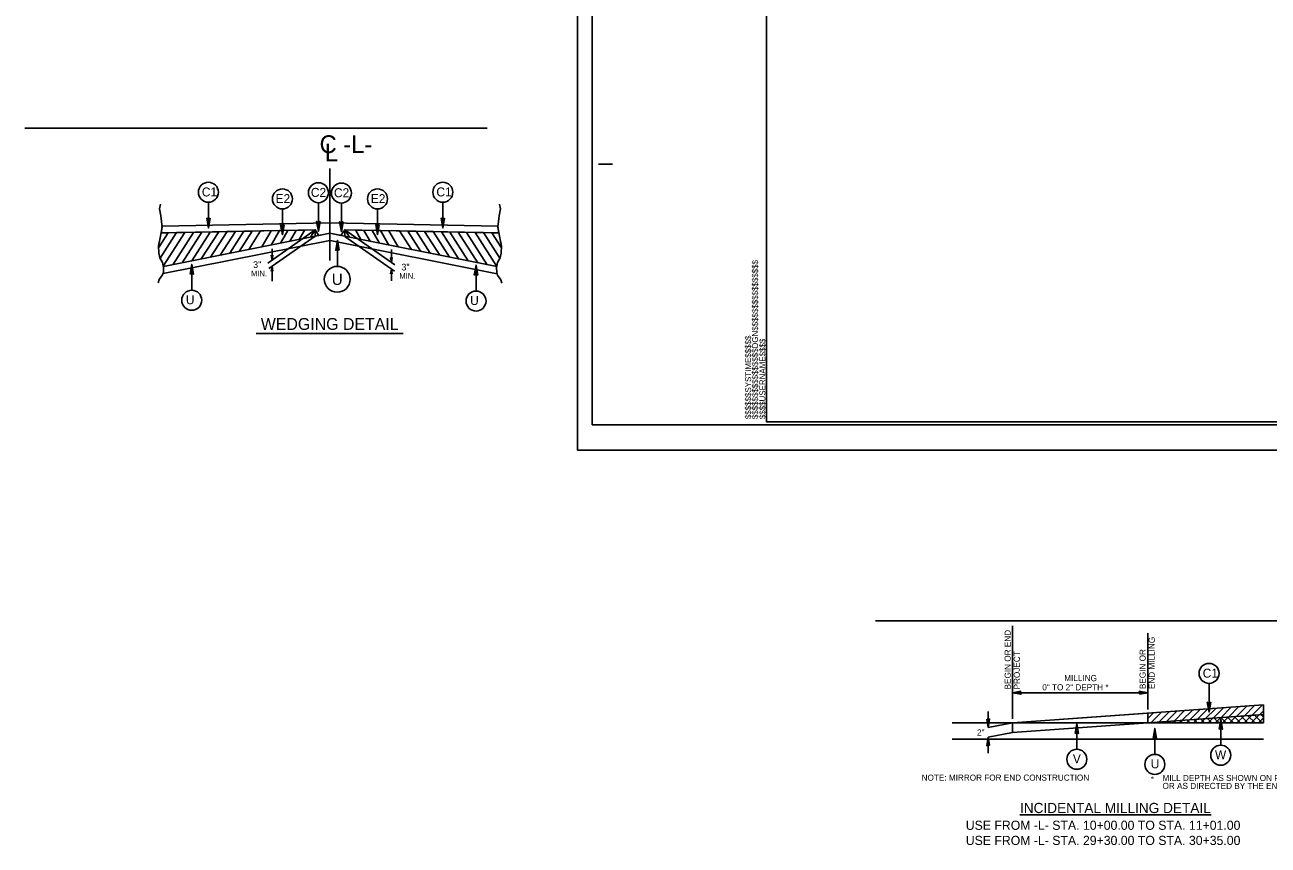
# Model space of a CAD drawing. Extents: x 2111095 to 2115970, y 670428 to 672393.
# Drawn here: x 2111095 to 2112193, y 670767 to 671492 of the extents above; entities that cross this region are included whole.
import ezdxf

# ---------------------------------------------------------------- set-up
doc = ezdxf.new("R2010")
doc.units = 0
for name, color, linetype in [('Old_Level_1', 7, 'Continuous'), ('Old_Level_11', 7, 'Continuous'), ('Old_Level_19', 7, 'Continuous'), ('Old_Level_20', 7, 'Continuous'), ('Old_Level_21', 7, 'Continuous'), ('Old_Level_3', 7, 'Continuous'), ('Prop Dimension', 7, 'Continuous'), ('Prop DSN Text', 7, 'Continuous'), ('Prop Shade Medium', 7, 'Continuous'), ('Sheet Cutting Line CELL', 7, 'Continuous'), ('Sheet Plot Border Inside CELL', 7, 'Continuous'), ('Sheet Plot Border Outside CELL', 7, 'Continuous'), ('Sheet Typical CELL', 7, 'Continuous')]:
    doc.layers.add(name, color=color, linetype=linetype)

msp = doc.modelspace()

# ---------------------------------------------------------------- linework, layer by layer
at = {"layer": 'Old_Level_1'}
for p, q in [((2111364.8, 671283.4), (2111364.8, 671364.8)), ((2111312.9, 671309.8), (2111304.6, 671295.6)), ((2111320.3, 671310), (2111312.9, 671297.2)), ((2111327.6, 671310.1), (2111321.1, 671298.9)), ((2111335, 671310.1), (2111329.4, 671300.5)), ((2111342.5, 671310.5), (2111337.6, 671302.2)), ((2111378, 671310.5), (2111422.1, 671279.6)), ((2111387.2, 671310.5), (2111392, 671302.2)), ((2111394.6, 671310.1), (2111400.2, 671300.5)), ((2111402, 671310.1), (2111408.6, 671298.9)), ((2111409.3, 671309.9), (2111416.8, 671297.2)), ((2111416.8, 671309.8), (2111425.1, 671295.6)), ((2111364.8, 671301.3), (2111217.5, 671271.9)), ((2111351.6, 671305), (2111310.7, 671276.3)), ((2111364.9, 671301.3), (2111512.5, 671271.8)), ((2111378, 671304.6), (2111421.7, 671274.1)), ((2111313.6, 671283.9), (2111312.9, 671288.2)), ((2111313.6, 671287.7), (2111312.9, 671288.2)), ((2111313.6, 671283.9), (2111313, 671288.1)), ((2111313.1, 671288.1), (2111313.6, 671283.9)), ((2111313.6, 671283.9), (2111313.2, 671288)), ((2111313.3, 671287.9), (2111313.6, 671283.9)), ((2111313.6, 671283.9), (2111313.4, 671287.8)), ((2111313.5, 671287.7), (2111313.6, 671283.9)), ((2111313.6, 671293.8), (2111313.6, 671283.9)), ((2111313.6, 671283.9), (2111314.4, 671288.2)), ((2111314.4, 671288.2), (2111313.6, 671287.7)), ((2111314.3, 671288.1), (2111313.6, 671283.9)), ((2111313.6, 671283.9), (2111314.2, 671288.1)), ((2111314.1, 671288), (2111313.6, 671283.9)), ((2111313.6, 671283.9), (2111314, 671287.9)), ((2111313.9, 671287.8), (2111313.6, 671283.9)), ((2111313.6, 671283.9), (2111313.8, 671287.7)), ((2111313.6, 671287.7), (2111313.6, 671283.9)), ((2111419, 671293.2), (2111419, 671281.8)), ((2111313.6, 671278.4), (2111312.9, 671274)), ((2111313, 671274.1), (2111313.6, 671278.4)), ((2111313.6, 671278.4), (2111313.1, 671274.2)), ((2111313.2, 671274.3), (2111313.6, 671278.4)), ((2111313.6, 671278.4), (2111313.3, 671274.4)), ((2111313.4, 671274.4), (2111313.6, 671278.4)), ((2111313.6, 671278.4), (2111313.5, 671274.5)), ((2111313.6, 671278.4), (2111313.6, 671265.4)), ((2111313.6, 671278.4), (2111314.4, 671274)), ((2111313.6, 671274.6), (2111313.6, 671278.4)), ((2111313.8, 671274.5), (2111313.6, 671278.4)), ((2111313.6, 671278.4), (2111313.9, 671274.4)), ((2111314, 671274.4), (2111313.6, 671278.4)), ((2111313.6, 671278.4), (2111314.1, 671274.3)), ((2111314.2, 671274.2), (2111313.6, 671278.4)), ((2111313.6, 671278.4), (2111314.3, 671274.1)), ((2111419, 671281.8), (2111418.2, 671286.2)), ((2111419, 671285.6), (2111418.2, 671286.2)), ((2111419, 671281.8), (2111418.3, 671286.1)), ((2111418.4, 671286), (2111419, 671281.8)), ((2111419, 671281.8), (2111418.6, 671285.9)), ((2111418.7, 671285.9), (2111419, 671281.8)), ((2111419, 671281.8), (2111418.8, 671285.8)), ((2111418.9, 671285.7), (2111419, 671281.8)), ((2111419, 671281.8), (2111419.8, 671286.2)), ((2111419.8, 671286.2), (2111419, 671285.6)), ((2111419.7, 671286.1), (2111419, 671281.8)), ((2111419, 671281.8), (2111419.5, 671286)), ((2111419.4, 671285.9), (2111419, 671281.8)), ((2111419, 671281.8), (2111419.3, 671285.9)), ((2111419.2, 671285.8), (2111419, 671281.8)), ((2111419, 671281.8), (2111419.1, 671285.7)), ((2111419, 671285.6), (2111419, 671281.8)), ((2111312.9, 671274), (2111313.6, 671274.6)), ((2111313.6, 671274.6), (2111314.4, 671274)), ((2111419, 671275.9), (2111418.2, 671271.6)), ((2111418.2, 671271.6), (2111419, 671272.1)), ((2111418.3, 671271.7), (2111419, 671275.9)), ((2111419, 671275.9), (2111418.4, 671271.7)), ((2111418.6, 671271.8), (2111419, 671275.9)), ((2111419, 671275.9), (2111418.7, 671271.9)), ((2111418.8, 671272), (2111419, 671275.9)), ((2111419, 671275.9), (2111418.9, 671272)), ((2111419, 671275.9), (2111419, 671265.7)), ((2111419, 671275.9), (2111419.8, 671271.6)), ((2111419, 671272.1), (2111419, 671275.9)), ((2111419.1, 671272), (2111419, 671275.9)), ((2111419, 671275.9), (2111419.2, 671272)), ((2111419.3, 671271.9), (2111419, 671275.9)), ((2111419, 671275.9), (2111419.4, 671271.8)), ((2111419.5, 671271.7), (2111419, 671275.9)), ((2111419, 671275.9), (2111419.7, 671271.7)), ((2111419, 671272.1), (2111419.8, 671271.6)), ((2112189.5, 670891), (2111967.7, 670875.1)), ((2112087.2, 670875.1), (2112087.2, 670883.7)), ((2112189.5, 670882.5), (2112087.2, 670875.1)), ((2112189.5, 670875.1), (2112189.5, 670891)), ((2112189.5, 670875.1), (2111914.5, 670875.1)), ((2112087.2, 670875.1), (2111967.7, 670866.6)), ((2111967.7, 670866.6), (2111967.7, 670875.1)), ((2112189.5, 670860.7), (2111914.5, 670860.7))]:
    msp.add_line(p, q, dxfattribs=at)
for points in [[(2111215.1, 671333.4), (2111214.3, 671329.1), (2111215.5, 671322.9), (2111216.5, 671312.9), (2111215.1, 671305), (2111213.4, 671296.4), (2111213.5, 671290), (2111214.6, 671285.9), (2111216.9, 671281.8), (2111217.7, 671277.3), (2111217.6, 671272.9), (2111216.8, 671270.8), (2111214, 671266.6), (2111213.1, 671263.7)], [(2111514.6, 671333.4), (2111515.4, 671329), (2111514.2, 671322.9), (2111513.1, 671312.9), (2111514.6, 671305), (2111516.3, 671296.4), (2111516.1, 671290), (2111515.1, 671285.9), (2111512.7, 671281.8), (2111511.9, 671277.3), (2111512.1, 671272.8), (2111512.8, 671270.7), (2111515.6, 671266.5), (2111516.5, 671263.6)], [(2111267.7, 671288.2), (2111281.2, 671309.2)], [(2111276.3, 671289.9), (2111288.8, 671309.4)], [(2111284.6, 671291.6), (2111296.2, 671309.5)], [(2111293, 671293.3), (2111303.5, 671309.7)], [(2111436.7, 671293.2), (2111426.1, 671309.7)], [(2111445, 671291.6), (2111433.5, 671309.5)], [(2111453.4, 671289.9), (2111440.9, 671309.4)], [(2111461.9, 671288.2), (2111448.4, 671309.2)], [(2111213.4, 671294.7), (2111222, 671308)], [(2111217.6, 671278.2), (2111216.9, 671281.8), (2111214.6, 671285.9), (2111213.5, 671290), (2111213.4, 671296.4), (2111214.2, 671300.4)], [(2111214.8, 671285.5), (2111229.3, 671308.2)], [(2111217.5, 671278.4), (2111236.7, 671308.3)], [(2111226, 671279.8), (2111244.2, 671308.3)], [(2111234.3, 671281.5), (2111251.6, 671308.4)], [(2111242.7, 671283.2), (2111258.9, 671308.6)], [(2111251, 671284.9), (2111266.5, 671308.9)], [(2111259.4, 671286.5), (2111273.9, 671309.1)], [(2111470.3, 671286.5), (2111455.8, 671309.1)], [(2111478.6, 671284.8), (2111463.2, 671308.9)], [(2111487, 671283.2), (2111470.7, 671308.6)], [(2111495.3, 671281.5), (2111478.1, 671308.4)], [(2111503.7, 671279.8), (2111485.5, 671308.3)], [(2111512.3, 671278.1), (2111492.9, 671308.3)], [(2111514.8, 671285.5), (2111500.3, 671308.2)], [(2111516.2, 671294.7), (2111507.7, 671308)], [(2111512.1, 671278.1), (2111512.7, 671281.8), (2111515.1, 671285.9), (2111516.1, 671290), (2111516.3, 671296.4), (2111515.5, 671300.4)]]:
    msp.add_lwpolyline(points, dxfattribs=at)
at = {"layer": 'Old_Level_11'}
for p, q in [((2111257.4, 671334.9), (2111257.4, 671312.1)), ((2111354.6, 671334.6), (2111354.6, 671309.3)), ((2111374.9, 671334.3), (2111374.9, 671308.9)), ((2111464.5, 671334.9), (2111464.5, 671312.1)), ((2111322.8, 671329.1), (2111322.8, 671306.3)), ((2111406.8, 671329.1), (2111406.8, 671306.3)), ((2111215.6, 671307.9), (2111216.5, 671313.8)), ((2111351.8, 671310.6), (2111215.6, 671307.9)), ((2111351.8, 671310.6), (2111215.6, 671307.9)), ((2111364.8, 671316.8), (2111216.5, 671313.8)), ((2111216.5, 671313.8), (2111364.8, 671316.8)), ((2111351.6, 671310.5), (2111309.8, 671281.2)), ((2111347.6, 671304.2), (2111351.6, 671310.5)), ((2111351.6, 671310.5), (2111351.6, 671305)), ((2111355.1, 671305.7), (2111351.8, 671310.6)), ((2111351.8, 671310.4), (2111355.1, 671305.7)), ((2111364.8, 671316.8), (2111513.2, 671313.8)), ((2111364.8, 671316.8), (2111513.2, 671313.8)), ((2111377.9, 671310.6), (2111374.5, 671305.7)), ((2111377.9, 671310.6), (2111374.5, 671305.7)), ((2111377.7, 671310.5), (2111377.9, 671310.5)), ((2111377.9, 671310.6), (2111514, 671307.8)), ((2111514, 671307.8), (2111377.9, 671310.6)), ((2111382.1, 671304.2), (2111378, 671310.5)), ((2111378, 671310.5), (2111378, 671305)), ((2111513.2, 671313.8), (2111514, 671307.8)), ((2111365, 671307.7), (2111217.6, 671278.2)), ((2111364.6, 671307.7), (2111355.1, 671305.7)), ((2111364.6, 671307.7), (2111512.1, 671278.1)), ((2111374.5, 671305.7), (2111364.6, 671307.7)), ((2111242.7, 671257.2), (2111242.7, 671280)), ((2111493.8, 671256.5), (2111493.8, 671279.4)), ((2111299.6, 671219.1), (2111429.4, 671219.1)), ((2111967.7, 670878.8), (2111967.7, 670961)), ((2112087.2, 670887), (2112087.2, 670954.4)), ((2112141.3, 670910), (2112141.3, 670884.7)), ((2112087.2, 670901.8), (2111967.7, 670901.8)), ((2111946.2, 670871.1), (2111946.2, 670885.1)), ((2111967.7, 670875.1), (2111946.2, 670871.1)), ((2112024.5, 670851.8), (2112024.5, 670874.6)), ((2112093.4, 670847.4), (2112093.4, 670870.2)), ((2112151.6, 670855.5), (2112151.6, 670878.3)), ((2111967.7, 670866.6), (2111946.2, 670862.5)), ((2111946.2, 670848.5), (2111946.2, 670862.5)), ((2111974.3, 670793.8), (2112143.1, 670793.8))]:
    msp.add_line(p, q, dxfattribs=at)
for points in [[(2111258.9, 671320.8), (2111257.4, 671312.1), (2111255.9, 671320.8), (2111257.4, 671319.7)], [(2111466, 671320.8), (2111464.5, 671312.1), (2111463, 671320.8), (2111464.5, 671319.7)], [(2111324.3, 671315), (2111322.8, 671306.3), (2111321.2, 671315), (2111322.8, 671313.9)], [(2111356.1, 671318), (2111354.6, 671309.3), (2111353, 671318), (2111354.6, 671316.9)], [(2111376.4, 671317.6), (2111374.9, 671308.9), (2111373.3, 671317.7), (2111374.9, 671316.6)], [(2111408.3, 671315), (2111406.8, 671306.3), (2111405.2, 671315), (2111406.8, 671313.9)], [(2111241.2, 671271.3), (2111242.7, 671280), (2111244.2, 671271.3), (2111242.7, 671272.4)], [(2111492.3, 671270.7), (2111493.8, 671279.4), (2111495.3, 671270.6), (2111493.8, 671271.8)], [(2111975.1, 670903.1), (2111967.7, 670901.8), (2111975.1, 670900.5), (2111974.2, 670901.8)], [(2112079.8, 670900.5), (2112087.2, 670901.8), (2112079.7, 670903.1), (2112080.7, 670901.8)], [(2112142.8, 670893.4), (2112141.3, 670884.7), (2112139.7, 670893.4), (2112141.3, 670892.3)], [(2111944.9, 670878.5), (2111946.2, 670871.1), (2111947.5, 670878.5), (2111946.2, 670877.6)], [(2112023, 670865.9), (2112024.5, 670874.6), (2112026, 670865.9), (2112024.5, 670867)], [(2112091.9, 670861.5), (2112093.4, 670870.2), (2112095, 670861.5), (2112093.4, 670862.6)], [(2112150.1, 670869.6), (2112151.6, 670878.3), (2112153.1, 670869.6), (2112151.6, 670870.7)], [(2111947.5, 670855.1), (2111946.2, 670862.5), (2111944.9, 670855), (2111946.2, 670856)]]:
    msp.add_lwpolyline(points, close=True, dxfattribs=at)
for centre in [(2111257.4, 671343.8), (2111322.8, 671337.9), (2111354.6, 671343.4), (2111374.9, 671343.1), (2111406.8, 671337.9), (2111464.5, 671343.8), (2111242.7, 671248.4), (2111493.8, 671247.7), (2112141.3, 670918.9), (2112024.5, 670843), (2112151.6, 670846.6), (2112093.4, 670838.5)]:
    msp.add_circle(centre, 8.84, dxfattribs=at)
at = {"layer": 'Old_Level_19'}
for p, q in [((2111750.5, 671446.9), (2111750.5, 671141)), ((2111095.3, 671400.3), (2111503.5, 671400.3)), ((2111750.5, 671141), (2112120.6, 671141)), ((2111846.6, 670965.3), (2112254.8, 670965.3))]:
    msp.add_line(p, q, dxfattribs=at)
at = {"layer": 'Prop DSN Text'}
msp.add_line((2111371.5, 671278.3), (2111371.5, 671301.4), dxfattribs=at)
msp.add_lwpolyline([(2111373, 671292.5), (2111371.5, 671293.6), (2111369.9, 671292.5), (2111371.5, 671301.4)], close=True, dxfattribs=at)
msp.add_circle((2111371.2, 671266.9), 11.4, dxfattribs=at)
at = {"layer": 'Prop Shade Medium'}
for p, q in [((2112092.3, 670884.1), (2112087.2, 670878.9)), ((2112099.2, 670884.5), (2112090, 670875.3)), ((2112106, 670885), (2112096.8, 670875.8)), ((2112112.9, 670885.5), (2112103.7, 670876.3)), ((2112119.7, 670886), (2112110.5, 670876.8)), ((2112126.6, 670886.5), (2112117.4, 670877.3)), ((2112133.4, 670887), (2112124.2, 670877.8)), ((2112140.3, 670887.5), (2112131.1, 670878.3)), ((2112147.2, 670888), (2112137.9, 670878.8)), ((2112154, 670888.5), (2112144.8, 670879.3)), ((2112160.9, 670889), (2112151.6, 670879.7)), ((2112167.7, 670889.5), (2112158.5, 670880.2)), ((2112174.6, 670889.9), (2112165.4, 670880.7)), ((2112171.9, 670881.2), (2112165.8, 670875.1)), ((2112175.5, 670875.1), (2112169.6, 670881)), ((2112181.4, 670890.4), (2112172.2, 670881.2)), ((2112178.7, 670881.7), (2112172.2, 670875.1)), ((2112181.9, 670875.1), (2112175.5, 670881.5)), ((2112185.6, 670882.2), (2112178.6, 670875.1)), ((2112188.3, 670890.9), (2112179.1, 670881.7)), ((2112188.2, 670875.1), (2112181.5, 670881.9)), ((2112189.5, 670885.8), (2112185.9, 670882.2)), ((2112189.5, 670880.2), (2112187.4, 670882.3)), ((2112089.6, 670875.3), (2112089.5, 670875.1)), ((2112092.8, 670875.1), (2112092.4, 670875.5)), ((2112096.5, 670875.8), (2112095.8, 670875.1)), ((2112099.1, 670875.1), (2112098.3, 670875.9)), ((2112103.4, 670876.3), (2112102.2, 670875.1)), ((2112105.5, 670875.1), (2112104.3, 670876.4)), ((2112110.2, 670876.8), (2112108.6, 670875.1)), ((2112111.9, 670875.1), (2112110.2, 670876.8)), ((2112117.1, 670877.3), (2112114.9, 670875.1)), ((2112118.2, 670875.1), (2112116.2, 670877.2)), ((2112123.9, 670877.8), (2112121.3, 670875.1)), ((2112124.6, 670875.1), (2112122.1, 670877.6)), ((2112130.8, 670878.3), (2112127.7, 670875.1)), ((2112131, 670875.1), (2112128, 670878.1)), ((2112137.6, 670878.7), (2112134, 670875.1)), ((2112137.3, 670875.1), (2112134, 670878.5)), ((2112143.7, 670875.1), (2112139.9, 670878.9)), ((2112144.5, 670879.2), (2112140.4, 670875.1)), ((2112150.1, 670875.1), (2112145.9, 670879.3)), ((2112151.3, 670879.7), (2112146.7, 670875.1)), ((2112156.4, 670875.1), (2112151.8, 670879.8)), ((2112158.2, 670880.2), (2112153.1, 670875.1)), ((2112162.8, 670875.1), (2112157.7, 670880.2)), ((2112165, 670880.7), (2112159.5, 670875.1)), ((2112169.1, 670875.1), (2112163.7, 670880.6)), ((2112189.5, 670879.7), (2112184.9, 670875.1))]:
    msp.add_line(p, q, dxfattribs=at)
for points in [[(2111303.5, 671309.6), (2111320.3, 671310), (2111342.4, 671310.4), (2111351.8, 671310.6), (2111355.1, 671305.7), (2111364.6, 671307.7), (2111364.8, 671307.6), (2111364.8, 671307.6), (2111364.8, 671316.8), (2111364.8, 671316.8), (2111216.5, 671313.8), (2111216.4, 671313.7), (2111216.5, 671312.9), (2111215.6, 671308), (2111215.6, 671307.9), (2111221.9, 671308), (2111229.3, 671308.1), (2111236.7, 671308.3), (2111266.4, 671308.9), (2111273.8, 671309), (2111281.2, 671309.2), (2111288.7, 671309.3), (2111296.1, 671309.5), (2111303.5, 671309.6)], [(2111426.2, 671309.6), (2111433.5, 671309.5), (2111440.9, 671309.3), (2111448.5, 671309.2), (2111455.8, 671309), (2111463.2, 671308.9), (2111493, 671308.3), (2111500.3, 671308.1), (2111507.7, 671308), (2111514, 671307.8), (2111513.1, 671312.9), (2111513.2, 671313.7), (2111513.2, 671313.8), (2111364.8, 671316.8), (2111364.8, 671316.8), (2111364.8, 671307.6), (2111364.8, 671307.6), (2111374.5, 671305.7), (2111377.9, 671310.5), (2111377.9, 671310.6), (2111387.2, 671310.4), (2111409.3, 671309.9), (2111409.3, 671309.9), (2111409.3, 671309.9), (2111426.2, 671309.6)]]:
    msp.add_lwpolyline(points, dxfattribs=at)
msp.add_lwpolyline([(2112087.2, 670875.1), (2112087.2, 670883.7), (2111967.7, 670875.1), (2111967.7, 670866.6)], close=True, dxfattribs=at)
at = {"layer": 'Sheet Cutting Line CELL'}
for p, q in [((2111583.5, 672216), (2111583.5, 671116)), ((2111583.5, 671116), (2113267.5, 671116))]:
    msp.add_line(p, q, dxfattribs=at)
at = {"layer": 'Sheet Plot Border Inside CELL'}
msp.add_lwpolyline([(2113263, 672193.6), (2111596.5, 672193.6), (2111596.5, 671138.5), (2113263, 671138.5)], close=True, dxfattribs=at)
at = {"layer": 'Sheet Plot Border Outside CELL'}
msp.add_lwpolyline([(2113267.5, 672216), (2111583.5, 672216), (2111583.5, 671116), (2113267.5, 671116)], close=True, dxfattribs=at)
at = {"layer": 'Sheet Typical CELL'}
for p, q in [((2111602, 671368.5), (2111614.5, 671368.5)), ((2111750.5, 671141), (2111750.5, 671141)), ((2111750.5, 671141), (2111750.5, 671141)), ((2111750.5, 671141), (2111750.5, 671141)), ((2111750.5, 671141), (2111750.5, 671141)), ((2111750.5, 671141), (2111750.5, 671141)), ((2111750.5, 671141), (2111750.5, 671141))]:
    msp.add_line(p, q, dxfattribs=at)
msp.add_lwpolyline([(2113250.5, 672191), (2111750.5, 672191), (2111750.5, 671141), (2113250.5, 671141)], close=True, dxfattribs=at)
msp.add_lwpolyline([(2111788, 671141), (2111788, 671141)], dxfattribs=at)

# ---------------------------------------------------------------- texts
at = {"layer": 'Old_Level_1'}
for s, height, p in [('C -L- ', 15.67, (2111355.6, 671378.4)), ('L', 15.7, (2111360.2, 671371))]:
    msp.add_text(s, height=height, rotation=359.9946, dxfattribs=at).set_placement(p)
at = {"layer": 'Old_Level_11'}
for s, p in [('BEGIN OR END', (2111966.1, 670904.7)), ('END MILLING', (2112093.4, 670905)), ('PROJECT', (2111974.2, 670904.7)), ('BEGIN OR', (2112085.3, 670905))]:
    msp.add_text(s, height=5.4, rotation=90, dxfattribs=at).set_placement(p)
for s, height, p in [('MILLING', 5.4, (2112013.4, 670912)), ('0" TO 2" DEPTH *', 5.4, (2111994, 670903.9)), ('2"', 5.4, (2111936.4, 670864)), ('NOTE: MIRROR FOR END CONSTRUCTION', 5.4, (2111887.4, 670824.1)), ('*', 5.4, (2112089.9, 670822.8)), ('MILL DEPTH AS SHOWN ON PLANS', 5.4, (2112100.2, 670823.8)), ('OR AS DIRECTED BY THE ENGINEER', 5.4, (2112100.2, 670816.8)), ('INCIDENTAL MILLING DETAIL', 9, (2111974.3, 670795.5)), ('USE FROM -L- STA. 10+00.00 TO STA. 11+01.00', 8.1, (2111926.4, 670780.7)), ('USE FROM -L- STA. 29+30.00 TO STA. 30+35.00 ', 8.1, (2111926.4, 670767.3))]:
    msp.add_text(s, height=height, dxfattribs=at).set_placement(p)
at = {"layer": 'Old_Level_20'}
for s, height, p in [('C1', 7.91, (2111251.6, 671340.1)), ('E2', 7.91, (2111316.7, 671334.2)), ('C2', 7.91, (2111347.9, 671339.7)), ('C2', 7.91, (2111368.3, 671339.4)), ('E2', 7.91, (2111400.8, 671334.2)), ('C1', 7.91, (2111458.8, 671340.1)), ('3"', 5.93, (2111296.9, 671276.9)), ('3"', 5.93, (2111427.9, 671274.7)), ('U', 7.91, (2111237.5, 671244.9)), ('U', 7.91, (2111488.6, 671244.2)), ('C1', 7.91, (2112135.7, 670915.1)), ('W', 7.91, (2112146.5, 670843.1)), ('V', 7.91, (2112021, 670839.5)), ('U', 7.91, (2112089.8, 670835))]:
    msp.add_text(s, height=height, rotation=359.9946, dxfattribs=at).set_placement(p)
at = {"layer": 'Old_Level_21'}
for p in [(2111295.1, 671269.6), (2111426.1, 671267.4)]:
    msp.add_text('MIN.', height=4.96, rotation=359.9946, dxfattribs=at).set_placement(p)
at = {"layer": 'Old_Level_3'}
msp.add_text('WEDGING DETAIL', height=10.5, rotation=359.9946, dxfattribs=at).set_placement((2111303.7, 671222.2))
at = {"layer": 'Prop Dimension'}
msp.add_text('U', height=10, rotation=0, dxfattribs=at).set_placement((2111366.4, 671261.9))
at = {"layer": 'Sheet Typical CELL'}
for s, p in [('$$$$$$$$$$$$$$$$DGN$$$$$$$$$$$$$$$$', (2111742.9, 671143.4)), ('$$$$$$SYSTIME$$$$$', (2111736.8, 671143.4)), ('$$$$USERNAME$$$$', (2111749.4, 671143.4))]:
    msp.add_text(s, height=5.25, rotation=90, dxfattribs=at).set_placement(p)

doc.saveas('drawing.dxf')
